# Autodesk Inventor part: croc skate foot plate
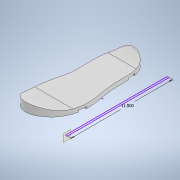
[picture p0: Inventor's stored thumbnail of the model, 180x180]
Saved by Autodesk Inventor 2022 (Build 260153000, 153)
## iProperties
Created: 2021-06
Part Number: croc skate foot plate
Material: Generic
Document SubType Name: Modeling
Designer: garre
Density: 1 g/cm^3
Appearance: Default
Author: garre
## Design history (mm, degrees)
sketch "Sketch1"
  geometry: L1 (0, 0)-(0, 304.8); L2 (0, 0)-(76.2, 0); 16 further points
  constraints: 4 end point, 1 coincident, 1 horizontal, 1 point on line, 1 vertical, 15 other
  dimensions: "d0" = 25.4 distance from line of L1 point (25.4, 6.35); "d1" = 6.35 distance from line of L2 point (25.4, 6.35); "d2" = 31.75 distance from line of L1 point (-31.75, 19.05); "d3" = 19.05 distance from line of point (-31.75, 19.05) L2; "d4" = 44.45 distance from line of L1 point (44.45, 63.5); "d5" = 63.5 distance from line of L2 point (44.45, 63.5); "d6" = 76.2 distance of L1.start L2.end; "d7" = 304.8 distance of L1.start L1.end; "d8" = 44.45 distance from line of L1 point (-44.45, 88.9); "d9" = 88.9 distance from line of L2 point (-44.45, 88.9); "d10" = 50.8 distance from line of L1 point (-50.8, 152.4); "d11" = 152.4 distance from line of L2 point (-50.8, 152.4); "d12" = 44.45 distance from line of L1 point (44.45, 133.35); "d13" = 133.35 distance from line of L2 point (44.45, 133.35); "d14" = 57.15 distance from line of L1 point (57.15, 196.85); "d15" = 196.85 distance from line of L2 point (57.15, 196.85); "d16" = 50.8 distance from line of L1 point (-50.8, 222.25); "d17" = 222.25 distance from line of L2 point (-50.8, 222.25); "d18" = 31.75 distance from line of L1 point (-31.75, 260.35); "d19" = 260.35 distance from line of L2 point (-31.75, 260.35); "d20" = 57.15 distance from line of L1 point (57.15, 273.05); "d21" = 273.05 distance from line of L2 point (57.15, 273.05); "d22" = 285.75 distance from line of L2 point (0, 285.75); "d23" = 292.1 distance from line of L2 point (25.4, 292.1); "d24" = 19.05 distance from line of L1 point (-19.05, 273.05); "d25" = 273.05 distance from line of L2 point (-19.05, 273.05)
extrude "Extrusion1" new body sketch "Sketch1" distance "d26" = 25.4; taper "d27" = 0 deg
sketch "Sketch4"
  geometry: L1 (90.123, 0)-(95.236, 0); L2 (95.236, 0)-(95.236, 292.1); L3 (95.236, 292.1)-(90.123, 292.1); L4 (90.123, 292.1)-(90.123, 0); 1 further point
  constraints: 8 end point, 2 parallel, 1 horizontal, 1 perpendicular
  dimensions: "d33" = 292.1 distance of L1.end L2.end
workplane "Work Plane1"
sketch "Sketch5"
  geometry: L1 (292.1, -6.35)-(0, -6.35) reference; L2 (0, -6.35)-(0, 25.4); L3 (0, 25.4)-(292.1, 25.4); L4 (292.1, 25.4)-(292.1, -6.35); L5 (292.1, -6.35)-(0, -6.35); L6 (63.5, 12.7)-(254, 12.7); A1 r 165.1 centre (63.5, 177.8) between (0, 25.4) and (63.5, 12.7); A2 r 63.5 centre (254, 76.2) between (254, 12.7) and (292.1, 25.4); 1 further point
  constraints: 10 end point, 4 point on circle, 2 centre point, 2 perpendicular, 2 tangent, 1 horizontal, 1 vertical
  dimensions: "d36" = 31.75 distance of L1.end L2.end; "d37" = 190.5 distance of L6.start L6.end; "d38" = 38.1 distance from line of L4 L6.end; "d40" = 19.05 distance between parallel lines of L1 L6
extrude "Extrusion4" cut sketch "Sketch5" distance "d42" = 207.9625; taper "d43" = 0 deg
sketch "Sketch6"
  geometry: L1 (-20.786, 292.1)-(-25.4, 292.1) reference; L2 (-23.093, 292.1)-(0, 292.1); L3 (0, 292.1)-(-47.789, 292.1); L4 (54.325, 215.9)-(-70.012, 215.9); L5 (-70.012, 215.9)-(-70.012, 196.85); L6 (-70.012, 196.85)-(58.438, 196.85); L7 (58.438, 196.85)-(58.438, 215.9); L8 (58.438, 215.9)-(54.325, 215.9); L9 (49.579, 63.5)-(-58.622, 63.5); L10 (-58.622, 63.5)-(-58.622, 44.45); L11 (-58.622, 44.45)-(49.579, 44.45); L12 (49.579, 44.45)-(49.579, 63.5); 1 further point
  constraints: 22 end point, 7 perpendicular, 3 horizontal, 2 point on line, 1 midpoint
  dimensions: "d44" = 76.2 distance between parallel lines of L4 L2; "d45" = 19.05 distance between parallel lines of L6 L4; "d46" = 19.05 distance of L9.end L10.end; "d47" = 44.45 vertical distance of point (0, 0) L11.end
extrude "Extrusion5" cut sketch "Sketch6" distance "d48" = 5.08; taper "d49" = 0 deg
feature "FaceDraft1" dims angle "d50" = 15 deg
feature "FaceDraft2" dims angle "d51" = 15 deg
feature "FaceDraft3" dims angle "d52" = 15 deg
feature "FaceDraft4" dims angle "d53" = 15 deg
sketch "Sketch7"
  geometry: L1 (12.7, 147.902)-(34.013, 122.502); L2 (-12.7, 147.902)-(-34.013, 122.502); L3 (34.013, 122.502)-(-34.013, 122.502); L4 (-12.7, 147.902)-(-58.181, 147.902); L5 (12.7, 147.902)-(54.892, 147.902); 1 further point
  constraints: 10 end point, 2 horizontal
sketch "Sketch9"
  geometry: L1 (2.54, 80.429)-(-2.54, 80.429); L2 (-2.54, 80.429)-(-2.54, 24.539); L3 (-2.54, 24.539)-(2.54, 24.539); L4 (2.54, 24.539)-(2.54, 80.429); L5 (0, 0)-(-12.229, 0) reference; L6 (0, 0)-(0, -2.992)
  constraints: 10 end point, 2 parallel, 1 horizontal, 1 perpendicular, 1 vertical
  dimensions: "d65" = 5.08 distance of L3.end L2.end; "d66" = 55.88937 distance of L3.end L1.start; "d67" = 2.54 distance between parallel lines of L6 L4
extrude "Extrusion7" join sketch "Sketch9" distance "d68" = 5.08; taper "d69" = 0 deg
sketch "Sketch10"
  geometry: L1 (0, 0)-(-12.229, 0) reference; L2 (0, 0)-(0, -7.512); L3 (2.54, 223.005)-(-2.54, 223.005); L4 (-2.54, 223.005)-(-2.54, 186.193); L5 (-2.54, 186.193)-(2.54, 186.193); L6 (2.54, 186.193)-(2.54, 223.005); L7 (-20.786, 292.1)-(-25.4, 292.1) reference
  constraints: 10 end point, 2 parallel, 1 horizontal, 1 perpendicular, 1 vertical
  dimensions: "d70" = 69.09509 distance between parallel lines of L7 L3; "d71" = 2.54 distance between parallel lines of L2 L6; "d72" = 5.08 distance between parallel lines of L6 L4
extrude "Extrusion8" join sketch "Sketch10" distance "d73" = 5.08; taper "d74" = 0 deg
body "Solid1"
body "Solid2"
body "Solid3"
other parameters: "d54" = 25.4, "d55" = 12.7
